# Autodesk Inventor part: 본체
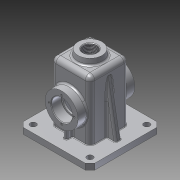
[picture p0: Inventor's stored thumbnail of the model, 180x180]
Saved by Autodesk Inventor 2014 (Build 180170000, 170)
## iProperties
Created: 2017-08
Part Number: 본체
Material: 알루미늄 6061
Document SubType Name: Modeling
Designer: user
Density: 2.71 g/cm^3
Appearance: 알루미늄 - 평지
Mass: 797.219 g
Surface Area: 899.488 cm^2
Volume: 294.177 cm^3
Author: user
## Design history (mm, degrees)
sketch "스케치1"
  geometry: L1 (32.5, -32.5)-(-32.5, -32.5); L2 (-32.5, -32.5)-(-32.5, 32.5); L3 (-32.5, 32.5)-(32.5, 32.5); L4 (32.5, 32.5)-(32.5, -32.5); L5 (32.5, -32.5)-(-32.5, 32.5); L6 (-32.5, -32.5)-(32.5, 32.5); 1 further point
  constraints: 12 end point, 2 midpoint, 2 parallel, 2 perpendicular, 1 horizontal
  dimensions: "d0" = 65 distance of L2.end L3.end
extrude "돌출1" new body sketch "스케치1" distance "d1" = 55; taper "d3" = 0 deg; dims "d2" = 55, "d4" = 0
fillet "모깎기1" dims "d5" = 8
fillet "모깎기2" dims "d6" = 8
feature "쉘1" dims "d7" = 5
sketch "스케치2"
  geometry: L1 (24.5, 32.5)-(-24.5, 32.5) reference; L2 (-32.5, 24.5)-(-32.5, -24.5) reference; L3 (-24.5, -32.5)-(24.5, -32.5) reference; L4 (32.5, -24.5)-(32.5, 24.5) reference; L5 (-60, -60)-(60, -60); L6 (60, -60)-(60, 60); L7 (60, 60)-(-60, 60); L8 (-60, 60)-(-60, -60); L9 (-60, -60)-(60, 60); L10 (60, -60)-(-60, 60); A1 r 8 centre (24.5, 24.5) between (32.5, 24.5) and (24.5, 32.5) reference; A2 r 8 centre (-24.5, 24.5) between (-24.5, 32.5) and (-32.5, 24.5) reference; A3 r 8 centre (-24.5, -24.5) between (-32.5, -24.5) and (-24.5, -32.5) reference; A4 r 8 centre (24.5, -24.5) between (24.5, -32.5) and (32.5, -24.5) reference; 1 further point
  constraints: 12 end point, 2 midpoint, 2 parallel, 2 perpendicular, 1 horizontal
  dimensions: "d8" = 120 distance of L6.end L7.end
extrude "돌출2" join sketch "스케치2" distance "d9" = 10; taper "d10" = 0 deg
sketch "스케치3"
  geometry: C1 r 27.5 at (24.5, -47); 1 further point
  constraints: 1 centre point, 1 coincident
  dimensions: "d11" = 55 diameter of C1
extrude "돌출3" join sketch "스케치3" distance "d12" = 15; taper "d13" = 0 deg
sketch "스케치4"
  geometry: C1 r 27.5 at (0, 0) reference; A1 r 21 centre (0, 0) between (0, 21) and (-21, 0); 2 further points
  constraints: 4 point on circle, 2 horizontal alignment, 2 vertical alignment, 1 centre point, 1 coincident
  dimensions: "d14" = 42 diameter of A1
hole "구멍1" sketch "스케치4" at (0, 21), (-21, 0), (0, -21), (21, 0) diameter "d15" = 3.242; stored, may be unused: countersink angle "d19" = 90 deg, drill point angle "d21" = 118 deg; dims "d16" = 8, "d17" = 4, "d18" = 2, "d20" = 10
sketch "스케치6"
  geometry: L1 (-24.5, -32.5)-(24.5, -32.5) reference; L2 (3, -42.5)-(-3, -42.5); L3 (-3, -42.5)-(-3, -32.5); L4 (-3, -32.5)-(3, -32.5); L5 (3, -32.5)-(3, -42.5); L6 (3, -42.5)-(-3, -32.5); L7 (-3, -42.5)-(3, -32.5); 4 further points
  constraints: 12 end point, 4 midpoint, 2 parallel, 2 vertical alignment, 1 horizontal, 1 perpendicular, 1 point on line
  dimensions: "d25" = 6 distance between parallel lines of L5 L3; "d26" = 10 distance of L4.end L2.start
extrude "돌출5" join sketch "스케치6" stored distance "d27" = 15; taper "d28" = 0 deg
node "작업 평면1"
sketch "스케치8"
  geometry: C1 r 20 at (0, 0); 1 further point
  constraints: 1 centre point, 1 coincident
  dimensions: "d30" = 40 diameter of C1
extrude "돌출6" join sketch "스케치8" stored distance "d31" = 15; taper "d32" = 7 deg
hole "구멍2" diameter "d35" = 22.835; stored, may be unused: countersink angle "d39" = 90 deg, drill point angle "d41" = 118 deg; dims "d33" = 10, "d34" = 10, "d36" = 8, "d37" = 4, "d38" = 2, "d40" = 10
sketch "스케치10"
  geometry: L1 (-32.5, -45)-(-32.5, 47) reference; L2 (60, -45)-(-60, -45) reference; L3 (32.5, 47)-(32.5, -45) reference; L4 (-32.5, 42.905)-(-48, -45); L5 (-60, -55)-(-60, -45) reference; 1 further point
  constraints: 2 end point, 2 point on line
  dimensions: "d42" = 10 deg angle of L5 L4; "d43" = 12 distance of L4.end L2.end
feature "리브1" sketch "스케치10" dims "d44" = 1, "d45" = 10, "d46" = 0, "d47" = 0, "d48" = 1, "d49" = 1
hole "구멍3" diameter "d52" = 30; stored, may be unused: countersink angle "d56" = 90 deg, drill point angle "d58" = 118 deg; dims "d50" = 10, "d51" = 10, "d53" = 8, "d54" = 35, "d55" = 17, "d57" = 10
fillet "모깎기3" dims "d59" = 0.3
chamfer "모따기1" distance "d60" = 8; stored, may be unused: second distance "d61" = 2, angle "d62" = 45 deg
sketch "스케치11"
  geometry: L1 (-60, 52)-(-60, -52) reference; L2 (52, 60)-(-52, 60) reference; 5 further points
  constraints: 2 horizontal alignment, 2 vertical alignment
  dimensions: "d63" = 95 distance of point (47.5, 47.5) point (-47.5, 47.5); "d64" = 95 distance of point (47.5, -47.5) point (47.5, 47.5); "d65" = 12.5 distance from line of point (-47.5, 47.5) L1; "d66" = 12.5 distance from line of L2 point (-47.5, 47.5)
hole "구멍4" sketch "스케치11" at (-47.5, 47.5), (47.5, 47.5), (47.5, -47.5), (-47.5, -47.5) diameter "d67" = 10; stored, may be unused: countersink angle "d71" = 90 deg, drill point angle "d73" = 118 deg; dims "d68" = 8, "d69" = 35, "d70" = 17, "d72" = 10
fillet "모깎기4" dims "d74" = 3
fillet "모깎기5" dims "d75" = 3
fillet "모깎기6" dims "d76" = 3
fillet "모깎기7" dims "d77" = 3
fillet "모깎기8" dims "d78" = 3
fillet "모깎기9" dims "d79" = 3
fillet "모깎기10" dims "d80" = 3
fillet "모깎기11" dims "d81" = 3
fillet "모깎기12" dims "d82" = 3
fillet "모깎기13" dims "d83" = 3
fillet "모깎기14" dims "d84" = 1
chamfer "모따기2" distance "d85" = 1; stored, may be unused: second distance "d86" = 2, angle "d87" = 45 deg
sketch "스케치12"
  geometry: L1 (57, 0)-(57, 91) reference; L2 (44.5, -18)-(4.5, -18) reference; 1 further point
  constraints: 1 other
  dimensions: "d88" = 32.5 distance from line of point (24.5, 8) L1; "d89" = 26 distance from line of point (24.5, 8) L2
feature "엠보싱1" sketch "스케치12" dims "d90" = 0.5, "d91" = 0
node "솔리드1"
mirror "대칭1"
mirror "대칭2"
mirror "대칭3"
other parameters: "d29" = 65
